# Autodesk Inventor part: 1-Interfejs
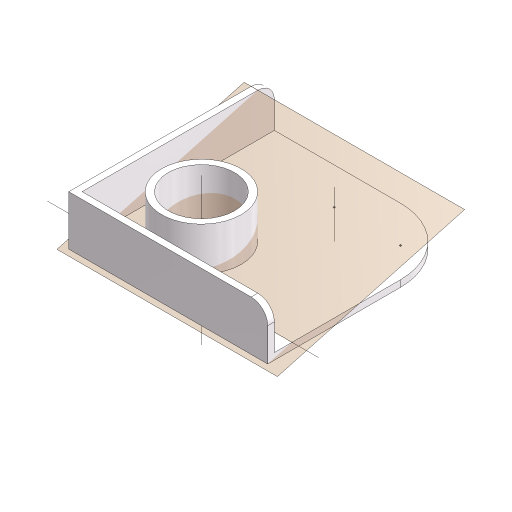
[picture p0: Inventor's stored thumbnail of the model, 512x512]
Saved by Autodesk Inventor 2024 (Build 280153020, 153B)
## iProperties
Company: ATC
Shininess: 50.0
Length Units: 11269
Angle Units: 11279
Time Units: 11290
Mass Units: 11283
Length Display Precision: 3
Angle Display Precision: 2
Compacted: True
Part Number: 1-Interfejs
Document SubType Name: Modeling
Designer: Andrzej Jaskulski
Material: Kurs-AJ
Density: 1 g/cm^3
Mass: 11.2435 g
Surface Area: 118.754 cm^2
Volume: 11.2435 cm^3
Appearance: Kurs-AJ
Created: 2023-03
Checked By: A.J.
Engr Approved By: Andrzej Jaskulski
Mfg Approved By: Andrzej Jaskulski
Authority: A.J.
Density: 0.0
Volumn: 0.0
Area: 0.0
PropertySet Name: Model Information
Control State: 0
Master: False
Checked Out: False
Title: A.J.: Kurs R2024-MEP
Author: Andrzej Jaskulski
Revision Number: 1/24
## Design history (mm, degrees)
sketch "Sketch1"
  geometry: L1 (0, 0)-(60, 0); L2 (60, 0)-(60, 60); L3 (60, 60)-(0, 60); L4 (0, 60)-(0, 0)
  constraints: 8 end point, 2 parallel, 1 horizontal, 1 perpendicular, 1 other
  dimensions: "d0" = 60 distance of L1.start L1.end (= x); "d1" = 60 distance of L1.end L2.end (= y)
extrude "Extrusion1 Baza" new body sketch "Sketch1" distance "d2" = 15 (= h); taper "d3" = 0 deg
sketch "Sketch3"
  geometry: L1 (0, 0)-(0, 60) reference; L2 (60, 0)-(0, 0) reference; 1 further point
  dimensions: "d9" = 20 distance from line of L1 point (20, 20) (= Lx); "d10" = 20 distance from line of L2 point (20, 20) (= Ly)
hole "Hole1 Otwór" sketch "Sketch3" at (20, 20) diameter "d7" = 20 (= d); stored, may be unused: countersink angle "d18" = 60 deg, drill point angle "d20" = 118 deg; dims "d8" = 6, "d16" = 4, "d17" = 2, "d19" = 8
fillet "Fillet1 Zaokrąglenie1" dims "d4" = 20 (= d)
fillet "Fillet2 Zaokrąglenie2" dims "d5" = 5 (= 0.5 x r)
feature "Shell1 Ścianki1" dims "d6" = 2
workplane "Work Plane1 Przez dwie krawędzie"
workaxis "Work Axis1 Oś otworu"
workaxis "Work Axis2 Oś zaokrąglenia1"
workaxis "Work Axis3 Krawędź przecięcia"
workpoint "Work Point1 Punkt przebicia1"
workpoint "Work Point2 Punkt przebicia2"
node "Bryła1"
node "Korpusy bryłowe"
node "Korpusy powierzchniowe"
other parameters: "inna_glob" = 19 [user parameter], "inna2_glob" = 21 [user parameter], "x" = 60 [user parameter; used in 1 equation term], "y" = 60 [user parameter; used in 1 equation term], "h" = 15 [user parameter; used in 1 equation term], "Lx" = 20 [user parameter; used in 1 equation term], "Ly" = 20 [user parameter; used in 1 equation term], "L2" = 1 [user parameter], "d" = 20 (= 2 x r) [user parameter; used in 2 equation terms], "wys_glob" = 15 [user parameter]
